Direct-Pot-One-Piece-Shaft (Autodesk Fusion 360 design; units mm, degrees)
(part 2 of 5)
sketch "M5 stop reinforcement bolt" plane through (-36.1, 0, 0) normal (1, 0, 0) x axis (0, 0, -1)
  circle C1 centre (-79.6754, -33.9652) radius 2.7
extrude "Extrude12" cut sketch "M5 stop reinforcement bolt" along normal blind 27.2
work_plane "WorkPlane13" AlongDistance -15.4 ExtraOffset 0
sketch "M5 captive stop nut" plane through (-15.4, 0, 0) normal (1, 0, 0) x axis (0, 0, -1)
  line L1 (-83.8754, -31.5403) -> (-79.6754, -29.1154)
  line L2 (-83.8754, -36.39) -> (-83.8754, -31.5403)
  line L3 (-79.6754, -38.8149) -> (-83.8754, -36.39)
  line L4 (-75.4754, -36.39) -> (-79.6754, -38.8149)
  line L5 (-75.4754, -31.5403) -> (-75.4754, -36.39)
  line L6 (-79.6754, -29.1154) -> (-75.4754, -31.5403)
extrude "Extrude13" cut sketch "M5 captive stop nut" along normal blind 6.5
work_plane "WorkPlane14" AlongDistance -36 ExtraOffset 0
sketch "Broad stop support ear (1)" plane through (-36, 0, 0) normal (1, 0, 0) x axis (0, 0, -1)
  line L1 (-60, 44) -> (-60, 20)
  line L2 (-90, 44) -> (-60, 44)
  line L3 (-90, 20) -> (-90, 44)
  line L4 (-60, 20) -> (-90, 20)
extrude "Extrude14" add sketch "Broad stop support ear (1)" along normal blind 12
work_plane "WorkPlane15" AlongDistance -24 ExtraOffset 0
sketch "Integrated steel-core end stop (1)" plane through (-24, 0, 0) normal (1, 0, 0) x axis (0, 0, -1)
  circle C1 centre (-79.6754, 33.9652) radius 6
extrude "Extrude15" add sketch "Integrated steel-core end stop (1)" along normal blind 15
work_plane "WorkPlane16" AlongDistance -36.1 ExtraOffset 0
sketch "M5 stop reinforcement bolt (1)" plane through (-36.1, 0, 0) normal (1, 0, 0) x axis (0, 0, -1)
  circle C1 centre (-79.6754, 33.9652) radius 2.7
extrude "Extrude16" cut sketch "M5 stop reinforcement bolt (1)" along normal blind 27.2
work_plane "WorkPlane17" AlongDistance -15.4 ExtraOffset 0
sketch "M5 captive stop nut (1)" plane through (-15.4, 0, 0) normal (1, 0, 0) x axis (0, 0, -1)
  line L1 (-83.8754, 36.39) -> (-79.6754, 38.8149)
  line L2 (-83.8754, 31.5403) -> (-83.8754, 36.39)
  line L3 (-79.6754, 29.1154) -> (-83.8754, 31.5403)
  line L4 (-75.4754, 31.5403) -> (-79.6754, 29.1154)
  line L5 (-75.4754, 36.39) -> (-75.4754, 31.5403)
  line L6 (-79.6754, 38.8149) -> (-75.4754, 36.39)
extrude "Extrude17" cut sketch "M5 captive stop nut (1)" along normal blind 6.5
work_plane "WorkPlane13" AlongDistance -24 ExtraOffset 0
sketch "Restore shaft socket through stop-lug root" plane through (-24, 0, 0) normal (1, 0, 0) x axis (0, 0, -1)
  line L1 (-69.6247, 6.65) -> (-60.3753, 6.65)
  arc A1 centre (-65, 0) radius 8.1 clockwise from (-60.3753, 6.65) to (-69.6247, 6.65)
extrude "Extrude13" cut sketch "Restore shaft socket through stop-lug root" along normal blind 48
work_plane "WorkPlane10" AlongDistance -24.1 ExtraOffset 0
sketch "Cam sweep clearance through crossblock" plane through (-24.1, 0, 0) normal (1, 0, 0) x axis (0, 0, -1)
  circle C1 centre (-65, 0) radius 51
extrude "Extrude10" cut sketch "Cam sweep clearance through crossblock" along normal blind 48.2
work_plane "WorkPlane10" AlongDistance 36 ExtraOffset 0
sketch "Rigid sensor carriage support" plane through (36, 0, 0) normal (1, 0, 0) x axis (0, 0, -1)
  line L1 (-49, -18) -> (-49, -28)
  line L2 (-81, -18) -> (-49, -18)
  line L3 (-81, -28) -> (-81, -18)
  line L4 (-49, -28) -> (-81, -28)
extrude "Extrude10" add sketch "Rigid sensor carriage support" along normal blind 44
work_plane "WorkPlane11" AlongDistance -28.1 ExtraOffset 0
sketch "M3 sensor carriage heat set" plane through (0, -28.1, 0) normal (0, 1, 0) x axis (1, 0, 0)
  circle C1 centre (74, -65) radius 2
extrude "Extrude11" cut sketch "M3 sensor carriage heat set" along normal blind 6.8
work_plane "WorkPlane12" AlongDistance 36 ExtraOffset 0
sketch "Rigid sensor carriage support (1)" plane through (36, 0, 0) normal (1, 0, 0) x axis (0, 0, -1)
  line L1 (-49, 28) -> (-49, 18)
  line L2 (-81, 28) -> (-49, 28)
  line L3 (-81, 18) -> (-81, 28)
  line L4 (-49, 18) -> (-81, 18)
extrude "Extrude12" add sketch "Rigid sensor carriage support (1)" along normal blind 44
work_plane "WorkPlane13" AlongDistance 21.3 ExtraOffset 0
sketch "M3 sensor carriage heat set (1)" plane through (0, 21.3, 0) normal (0, 1, 0) x axis (1, 0, 0)
  circle C1 centre (74, -65) radius 2
extrude "Extrude13" cut sketch "M3 sensor carriage heat set (1)" along normal blind 6.8
work_plane "WorkPlane1" AlongDistance -24 ExtraOffset 0
sketch "Controlled follower end float" plane through (-24, 0, 0) normal (1, 0, 0) x axis (0, 0, -1)
  circle C1 centre (-12, -35) radius 6
extrude "Extrude1" new body sketch "Controlled follower end float" along normal blind 27.8 bodies "P21 Follower left axial spacer"
work_plane "WorkPlane2" AlongDistance -24.1 ExtraOffset 0
sketch "Pivot sleeve running clearance" plane through (-24.1, 0, 0) normal (1, 0, 0) x axis (0, 0, -1)
  circle C1 centre (-12, -35) radius 4.2
extrude "Extrude2" cut sketch "Pivot sleeve running clearance" along normal blind 28
work_plane "WorkPlane1" AlongDistance 20.2 ExtraOffset 0
sketch "Controlled follower end float" plane through (20.2, 0, 0) normal (1, 0, 0) x axis (0, 0, -1)
  circle C1 centre (-12, -35) radius 6
extrude "Extrude1" new body sketch "Controlled follower end float" along normal blind 3.8 bodies "P22 Follower right axial spacer"
work_plane "WorkPlane2" AlongDistance 20.1 ExtraOffset 0
sketch "Pivot sleeve running clearance" plane through (20.1, 0, 0) normal (1, 0, 0) x axis (0, 0, -1)
  circle C1 centre (-12, -35) radius 4.2
extrude "Extrude2" cut sketch "Pivot sleeve running clearance" along normal blind 4
work_plane "WorkPlane1" AlongDistance 3.1 ExtraOffset 0
sketch "Roller axle M3 nut" plane through (3.1, 0, 0) normal (1, 0, 0) x axis (0, 0, -1)
  line L1 (-14.75, 1.5877) -> (-12, 3.1754)
  line L2 (-14.75, -1.5877) -> (-14.75, 1.5877)
  line L3 (-12, -3.1754) -> (-14.75, -1.5877)
  line L4 (-9.25, -1.5877) -> (-12, -3.1754)
  line L5 (-9.25, 1.5877) -> (-9.25, -1.5877)
  line L6 (-12, 3.1754) -> (-9.25, 1.5877)
extrude "Extrude1" new body sketch "Roller axle M3 nut" along normal blind 2.4 bodies "HARDWARE Roller axle M3 nut"
work_plane "WorkPlane2" AlongDistance 3 ExtraOffset 0
sketch "Thread envelope" plane through (3, 0, 0) normal (1, 0, 0) x axis (0, 0, -1)
  circle C1 centre (-12, 0) radius 1.5
extrude "Extrude2" cut sketch "Thread envelope" along normal blind 2.6
work_plane "WorkPlane14" AlongDistance 23.9 ExtraOffset 0
sketch "Cam lateral service opening" plane through (23.9, 0, 0) normal (1, 0, 0) x axis (0, 0, -1)
  line L1 (-42.2047, 46.7373) -> (-43.8497, 47.5044)
  line L2 (-40.5875, 45.9133) -> (-42.2047, 46.7373)
  line L3 (-39, 45.0333) -> (-40.5875, 45.9133)
  line L4 (-37.4442, 44.0985) -> (-39, 45.0333)
  line L5 (-35.922, 43.11) -> (-37.4442, 44.0985)
  line L6 (-34.4352, 42.0689) -> (-35.922, 43.11)
  line L7 (-32.9856, 40.9766) -> (-34.4352, 42.0689)
  line L8 (-31.575, 39.8343) -> (-32.9856, 40.9766)
  line L9 (-30.2052, 38.6435) -> (-31.575, 39.8343)
  line L10 (-28.8778, 37.4057) -> (-30.2052, 38.6435)
  line L11 (-27.5943, 36.1222) -> (-28.8778, 37.4057)
  line L12 (-26.3565, 34.7948) -> (-27.5943, 36.1222)
  line L13 (-25.1657, 33.425) -> (-26.3565, 34.7948)
  line L14 (-24.0234, 32.0144) -> (-25.1657, 33.425)
  line L15 (-22.9311, 30.5648) -> (-24.0234, 32.0144)
  line L16 (-21.89, 29.078) -> (-22.9311, 30.5648)
  line L17 (-20.9015, 27.5558) -> (-21.89, 29.078)
  line L18 (-19.9667, 26) -> (-20.9015, 27.5558)
  line L19 (-19.0867, 24.4125) -> (-19.9667, 26)
  line L20 (-18.2627, 22.7953) -> (-19.0867, 24.4125)
  line L21 (-17.4956, 21.1503) -> (-18.2627, 22.7953)
  line L22 (-16.7864, 19.4795) -> (-17.4956, 21.1503)
  line L23 (-16.136, 17.785) -> (-16.7864, 19.4795)
  line L24 (-15.5451, 16.0689) -> (-16.136, 17.785)
  line L25 (-15.0144, 14.3331) -> (-15.5451, 16.0689)
  line L26 (-14.5446, 12.5799) -> (-15.0144, 14.3331)
  line L27 (-14.1363, 10.8114) -> (-14.5446, 12.5799)
  line L28 (-13.79, 9.0297) -> (-14.1363, 10.8114)
  line L29 (-13.5061, 7.237) -> (-13.79, 9.0297)
  line L30 (-13.2849, 5.4355) -> (-13.5061, 7.237)
  line L31 (-13.1267, 3.6273) -> (-13.2849, 5.4355)
  line L32 (-13.0317, 1.8148) -> (-13.1267, 3.6273)
  line L33 (-13, 0) -> (-13.0317, 1.8148)
  line L34 (-13.0317, -1.8148) -> (-13, 0)
  line L35 (-13.1267, -3.6273) -> (-13.0317, -1.8148)
  line L36 (-13.2849, -5.4355) -> (-13.1267, -3.6273)
  line L37 (-13.5061, -7.237) -> (-13.2849, -5.4355)
  line L38 (-13.79, -9.0297) -> (-13.5061, -7.237)
  line L39 (-14.1363, -10.8114) -> (-13.79, -9.0297)
  line L40 (-14.5446, -12.5799) -> (-14.1363, -10.8114)
  line L41 (-15.0144, -14.3331) -> (-14.5446, -12.5799)
  line L42 (-15.5451, -16.0689) -> (-15.0144, -14.3331)
  line L43 (-16.136, -17.785) -> (-15.5451, -16.0689)
  line L44 (-16.7864, -19.4795) -> (-16.136, -17.785)
  line L45 (-17.4956, -21.1503) -> (-16.7864, -19.4795)
  line L46 (-18.2627, -22.7953) -> (-17.4956, -21.1503)
  line L47 (-19.0867, -24.4125) -> (-18.2627, -22.7953)
  line L48 (-19.9667, -26) -> (-19.0867, -24.4125)
  line L49 (-20.9015, -27.5558) -> (-19.9667, -26)
  line L50 (-21.89, -29.078) -> (-20.9015, -27.5558)
  line L51 (-22.9311, -30.5648) -> (-21.89, -29.078)
  line L52 (-24.0234, -32.0144) -> (-22.9311, -30.5648)
  line L53 (-25.1657, -33.425) -> (-24.0234, -32.0144)
  line L54 (-26.3565, -34.7948) -> (-25.1657, -33.425)
  line L55 (-27.5943, -36.1222) -> (-26.3565, -34.7948)
  line L56 (-28.8778, -37.4057) -> (-27.5943, -36.1222)
  line L57 (-30.2052, -38.6435) -> (-28.8778, -37.4057)
  line L58 (-31.575, -39.8343) -> (-30.2052, -38.6435)
  line L59 (-32.9856, -40.9766) -> (-31.575, -39.8343)
  line L60 (-34.4352, -42.0689) -> (-32.9856, -40.9766)
  line L61 (-35.922, -43.11) -> (-34.4352, -42.0689)
  line L62 (-37.4442, -44.0985) -> (-35.922, -43.11)
  line L63 (-39, -45.0333) -> (-37.4442, -44.0985)
  line L64 (-40.5875, -45.9133) -> (-39, -45.0333)
  line L65 (-42.2047, -46.7373) -> (-40.5875, -45.9133)
  line L66 (-43.8497, -47.5044) -> (-42.2047, -46.7373)
  line L67 (-54.4248, -23.7522) -> (-43.8497, -47.5044)
  line L68 (-53.6024, -23.3686) -> (-54.4248, -23.7522)
  line L69 (-52.7937, -22.9566) -> (-53.6024, -23.3686)
  line L70 (-52, -22.5167) -> (-52.7937, -22.9566)
  line L71 (-51.2221, -22.0493) -> (-52, -22.5167)
  line L72 (-50.461, -21.555) -> (-51.2221, -22.0493)
  line L73 (-49.7176, -21.0344) -> (-50.461, -21.555)
  line L74 (-48.9928, -20.4883) -> (-49.7176, -21.0344)
  line L75 (-48.2875, -19.9172) -> (-48.9928, -20.4883)
  line L76 (-47.6026, -19.3218) -> (-48.2875, -19.9172)
  line L77 (-46.9389, -18.7028) -> (-47.6026, -19.3218)
  line L78 (-46.2972, -18.0611) -> (-46.9389, -18.7028)
  line L79 (-45.6782, -17.3974) -> (-46.2972, -18.0611)
  line L80 (-45.0828, -16.7125) -> (-45.6782, -17.3974)
  line L81 (-44.5117, -16.0072) -> (-45.0828, -16.7125)
  line L82 (-43.9656, -15.2824) -> (-44.5117, -16.0072)
  line L83 (-43.445, -14.539) -> (-43.9656, -15.2824)
  line L84 (-42.9507, -13.7779) -> (-43.445, -14.539)
  line L85 (-42.4833, -13) -> (-42.9507, -13.7779)
  line L86 (-42.0434, -12.2063) -> (-42.4833, -13)
  line L87 (-41.6314, -11.3976) -> (-42.0434, -12.2063)
  line L88 (-41.2478, -10.5752) -> (-41.6314, -11.3976)
  line L89 (-40.8932, -9.7398) -> (-41.2478, -10.5752)
  line L90 (-40.568, -8.8925) -> (-40.8932, -9.7398)
  line L91 (-40.2725, -8.0344) -> (-40.568, -8.8925)
  line L92 (-40.0072, -7.1666) -> (-40.2725, -8.0344)
  line L93 (-39.7723, -6.29) -> (-40.0072, -7.1666)
  line L94 (-39.5682, -5.4057) -> (-39.7723, -6.29)
  line L95 (-39.395, -4.5149) -> (-39.5682, -5.4057)
  line L96 (-39.253, -3.6185) -> (-39.395, -4.5149)
  line L97 (-39.1424, -2.7177) -> (-39.253, -3.6185)
  line L98 (-39.0633, -1.8137) -> (-39.1424, -2.7177)
  line L99 (-39.0158, -0.9074) -> (-39.0633, -1.8137)
  line L100 (-39, 0) -> (-39.0158, -0.9074)
  line L101 (-39.0158, 0.9074) -> (-39, 0)
  line L102 (-39.0633, 1.8137) -> (-39.0158, 0.9074)
  line L103 (-39.1424, 2.7177) -> (-39.0633, 1.8137)
  line L104 (-39.253, 3.6185) -> (-39.1424, 2.7177)
  line L105 (-39.395, 4.5149) -> (-39.253, 3.6185)
  line L106 (-39.5682, 5.4057) -> (-39.395, 4.5149)
  line L107 (-39.7723, 6.29) -> (-39.5682, 5.4057)
  line L108 (-40.0072, 7.1666) -> (-39.7723, 6.29)
  line L109 (-40.2725, 8.0344) -> (-40.0072, 7.1666)
  line L110 (-40.568, 8.8925) -> (-40.2725, 8.0344)
  line L111 (-40.8932, 9.7398) -> (-40.568, 8.8925)
  line L112 (-41.2478, 10.5752) -> (-40.8932, 9.7398)
  line L113 (-41.6314, 11.3976) -> (-41.2478, 10.5752)
  line L114 (-42.0434, 12.2063) -> (-41.6314, 11.3976)
  line L115 (-42.4833, 13) -> (-42.0434, 12.2063)
  line L116 (-42.9507, 13.7779) -> (-42.4833, 13)
  line L117 (-43.445, 14.539) -> (-42.9507, 13.7779)
  line L118 (-43.9656, 15.2824) -> (-43.445, 14.539)
  line L119 (-44.5117, 16.0072) -> (-43.9656, 15.2824)
  line L120 (-45.0828, 16.7125) -> (-44.5117, 16.0072)
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extrude "Extrude14" cut sketch "Cam lateral service opening" along normal blind 12.2
work_plane "WorkPlane15" AlongDistance 36 ExtraOffset 0
sketch "Clear service path beneath sensor rails" plane through (36, 0, 0) normal (1, 0, 0) x axis (0, 0, -1)
  line L1 (-48.9, -18) -> (-48.9, -28)
  line L2 (-56, -18) -> (-48.9, -18)
  line L3 (-56, -28) -> (-56, -18)
  line L4 (-48.9, -28) -> (-56, -28)
extrude "Extrude15" cut sketch "Clear service path beneath sensor rails" along normal blind 44.1
work_plane "WorkPlane16" AlongDistance 36 ExtraOffset 0
sketch "Clear service path beneath sensor rails (1)" plane through (36, 0, 0) normal (1, 0, 0) x axis (0, 0, -1)
  line L1 (-48.9, 28) -> (-48.9, 18)
  line L2 (-56, 28) -> (-48.9, 28)
  line L3 (-56, 18) -> (-56, 28)
  line L4 (-48.9, 18) -> (-56, 18)
extrude "Extrude16" cut sketch "Clear service path beneath sensor rails (1)" along normal blind 44.1
work_plane "WorkPlane11" AlongDistance -24 ExtraOffset 0
sketch "Raise mount clear of rail bolt axes" plane through (-24, 0, 0) normal (1, 0, 0) x axis (0, 0, -1)
  line L1 (-52, -44) -> (-52, -66)
  line L2 (-57, -44) -> (-52, -44)
  line L3 (-57, -66) -> (-57, -44)
  line L4 (-52, -66) -> (-57, -66)
extrude "Extrude11" add sketch "Raise mount clear of rail bolt axes" along normal blind 48
work_plane "WorkPlane12" AlongDistance -24 ExtraOffset 0
sketch "Close old block mounting hole" plane through (-24, 0, 0) normal (1, 0, 0) x axis (0, 0, -1)
  circle C1 centre (-44, -59) radius 2.01
extrude "Extrude12" add sketch "Close old block mounting hole" along normal blind 8.7
work_plane "WorkPlane13" AlongDistance -24.1 ExtraOffset 0
sketch "Raised M3 block insert" plane through (-24.1, 0, 0) normal (1, 0, 0) x axis (0, 0, -1)
  circle C1 centre (-52, -59) radius 2
extrude "Extrude13" cut sketch "Raised M3 block insert" along normal blind 8.9
work_plane "WorkPlane14" AlongDistance 15.3 ExtraOffset 0
sketch "Close old block mounting hole (1)" plane through (15.3, 0, 0) normal (1, 0, 0) x axis (0, 0, -1)
  circle C1 centre (-44, -59) radius 2.01
extrude "Extrude14" add sketch "Close old block mounting hole (1)" along normal blind 8.7
work_plane "WorkPlane15" AlongDistance 15.2 ExtraOffset 0
sketch "Raised M3 block insert (1)" plane through (15.2, 0, 0) normal (1, 0, 0) x axis (0, 0, -1)
  circle C1 centre (-52, -59) radius 2
extrude "Extrude15" cut sketch "Raised M3 block insert (1)" along normal blind 8.9
work_plane "WorkPlane18" AlongDistance -36 ExtraOffset 0
sketch "Close old plate mounting hole" plane through (-36, 0, 0) normal (1, 0, 0) x axis (0, 0, -1)
  circle C1 centre (-44, -59) radius 1.71
extrude "Extrude18" add sketch "Close old plate mounting hole" along normal blind 12
work_plane "WorkPlane19" AlongDistance -36.1 ExtraOffset 0
sketch "Raised M3 block fastener" plane through (-36.1, 0, 0) normal (1, 0, 0) x axis (0, 0, -1)
  circle C1 centre (-52, -59) radius 1.7
extrude "Extrude19" cut sketch "Raised M3 block fastener" along normal blind 12.2
work_plane "WorkPlane17" AlongDistance 24 ExtraOffset 0
sketch "Close old plate mounting hole" plane through (24, 0, 0) normal (1, 0, 0) x axis (0, 0, -1)
  circle C1 centre (-44, -59) radius 1.71
extrude "Extrude17" add sketch "Close old plate mounting hole" along normal blind 12
work_plane "WorkPlane18" AlongDistance 23.9 ExtraOffset 0
sketch "Raised M3 block fastener" plane through (23.9, 0, 0) normal (1, 0, 0) x axis (0, 0, -1)
  circle C1 centre (-52, -59) radius 1.7
extrude "Extrude18" cut sketch "Raised M3 block fastener" along normal blind 12.2
work_plane "WorkPlane16" AlongDistance -24 ExtraOffset 0
sketch "Close old block mounting hole (2)" plane through (-24, 0, 0) normal (1, 0, 0) x axis (0, 0, -1)
  circle C1 centre (-44, -51) radius 2.01
extrude "Extrude16" add sketch "Close old block mounting hole (2)" along normal blind 8.7
work_plane "WorkPlane17" AlongDistance -24.1 ExtraOffset 0
sketch "Raised M3 block insert (2)" plane through (-24.1, 0, 0) normal (1, 0, 0) x axis (0, 0, -1)
  circle C1 centre (-52, -51) radius 2
extrude "Extrude17" cut sketch "Raised M3 block insert (2)" along normal blind 8.9
work_plane "WorkPlane18" AlongDistance 15.3 ExtraOffset 0
sketch "Close old block mounting hole (3)" plane through (15.3, 0, 0) normal (1, 0, 0) x axis (0, 0, -1)
  circle C1 centre (-44, -51) radius 2.01
extrude "Extrude18" add sketch "Close old block mounting hole (3)" along normal blind 8.7
work_plane "WorkPlane19" AlongDistance 15.2 ExtraOffset 0
sketch "Raised M3 block insert (3)" plane through (15.2, 0, 0) normal (1, 0, 0) x axis (0, 0, -1)
  circle C1 centre (-52, -51) radius 2
extrude "Extrude19" cut sketch "Raised M3 block insert (3)" along normal blind 8.9
work_plane "WorkPlane20" AlongDistance -36 ExtraOffset 0
sketch "Close old plate mounting hole (1)" plane through (-36, 0, 0) normal (1, 0, 0) x axis (0, 0, -1)
  circle C1 centre (-44, -51) radius 1.71
extrude "Extrude20" add sketch "Close old plate mounting hole (1)" along normal blind 12
work_plane "WorkPlane21" AlongDistance -36.1 ExtraOffset 0
sketch "Raised M3 block fastener (1)" plane through (-36.1, 0, 0) normal (1, 0, 0) x axis (0, 0, -1)
  circle C1 centre (-52, -51) radius 1.7
extrude "Extrude21" cut sketch "Raised M3 block fastener (1)" along normal blind 12.2
work_plane "WorkPlane19" AlongDistance 24 ExtraOffset 0
sketch "Close old plate mounting hole (1)" plane through (24, 0, 0) normal (1, 0, 0) x axis (0, 0, -1)
  circle C1 centre (-44, -51) radius 1.71
extrude "Extrude19" add sketch "Close old plate mounting hole (1)" along normal blind 12
work_plane "WorkPlane20" AlongDistance 23.9 ExtraOffset 0
sketch "Raised M3 block fastener (1)" plane through (23.9, 0, 0) normal (1, 0, 0) x axis (0, 0, -1)
  circle C1 centre (-52, -51) radius 1.7
extrude "Extrude20" cut sketch "Raised M3 block fastener (1)" along normal blind 12.2
work_plane "WorkPlane20" AlongDistance 51.9 ExtraOffset 0
sketch "Continue adjuster bore" plane through (0, 0, 51.9) normal (0, 0, 1) x axis (1, 0, 0)
  circle C1 centre (12, -55) radius 2.2
extrude "Extrude20" cut sketch "Continue adjuster bore" along normal blind 5.2
work_plane "WorkPlane21" AlongDistance 51.9 ExtraOffset 0
sketch "Continue guide bore" plane through (0, 0, 51.9) normal (0, 0, 1) x axis (1, 0, 0)
  circle C1 centre (5, -55) radius 1.7
extrude "Extrude21" cut sketch "Continue guide bore" along normal blind 5.2
work_plane "WorkPlane22" AlongDistance 51.9 ExtraOffset 0
sketch "Continue guide bore (1)" plane through (0, 0, 51.9) normal (0, 0, 1) x axis (1, 0, 0)
  circle C1 centre (19, -55) radius 1.7
extrude "Extrude22" cut sketch "Continue guide bore (1)" along normal blind 5.2
work_plane "WorkPlane23" AlongDistance -24.1 ExtraOffset 0
sketch "Preserve cam sweep clearance" plane through (-24.1, 0, 0) normal (1, 0, 0) x axis (0, 0, -1)
  circle C1 centre (-65, 0) radius 51
extrude "Extrude23" cut sketch "Preserve cam sweep clearance" along normal blind 48.2
work_plane "WorkPlane1" AlongDistance -23.85 ExtraOffset 0
sketch "Controlled rotor axial clearance" plane through (-23.85, 0, 0) normal (1, 0, 0) x axis (0, 0, -1)
  circle C1 centre (-65, 0) radius 10
extrude "Extrude1" new body sketch "Controlled rotor axial clearance" along normal blind 16.85 bodies "P23 Left rotor thrust spacer"
work_plane "WorkPlane2" AlongDistance -23.95 ExtraOffset 0
sketch "Free spacer bore" plane through (-23.95, 0, 0) normal (1, 0, 0) x axis (0, 0, -1)
  circle C1 centre (-65, 0) radius 8.2
extrude "Extrude2" cut sketch "Free spacer bore" along normal blind 17.05
work_plane "WorkPlane1" AlongDistance 7 ExtraOffset 0
sketch "Controlled rotor axial clearance" plane through (7, 0, 0) normal (1, 0, 0) x axis (0, 0, -1)
  circle C1 centre (-65, 0) radius 10
extrude "Extrude1" new body sketch "Controlled rotor axial clearance" along normal blind 16.85 bodies "P24 Right rotor thrust spacer"
work_plane "WorkPlane2" AlongDistance 6.9 ExtraOffset 0
sketch "Free spacer bore" plane through (6.9, 0, 0) normal (1, 0, 0) x axis (0, 0, -1)
  circle C1 centre (-65, 0) radius 8.2
extrude "Extrude2" cut sketch "Free spacer bore" along normal blind 17.05
work_plane "WorkPlane22" AlongDistance -76 ExtraOffset 0
sketch "Restore rail bolt clearance after hole filling" plane through (0, -76, 0) normal (0, 1, 0) x axis (1, 0, 0)
  circle C1 centre (-30, -45) radius 2.7
extrude "Extrude22" cut sketch "Restore rail bolt clearance after hole filling" along normal blind 22
work_plane "WorkPlane23" AlongDistance 54 ExtraOffset 0
sketch "Restore rail bolt clearance after hole filling (1)" plane through (0, 54, 0) normal (0, 1, 0) x axis (1, 0, 0)
  circle C1 centre (-30, -45) radius 2.7
work_plane "WorkPlane24" AlongDistance -55 ExtraOffset 0
sketch "Restore rail head access after hole filling" plane through (0, -55, 0) normal (0, 1, 0) x axis (1, 0, 0)
  circle C1 centre (-30, -45) radius 5.3
extrude "Extrude24" cut sketch "Restore rail head access after hole filling" along normal blind 12
work_plane "WorkPlane25" AlongDistance 43 ExtraOffset 0
sketch "Restore rail head access after hole filling (1)" plane through (0, 43, 0) normal (0, 1, 0) x axis (1, 0, 0)
  circle C1 centre (-30, -45) radius 5.3
work_plane "WorkPlane21" AlongDistance -76 ExtraOffset 0
sketch "Restore rail bolt clearance after hole filling" plane through (0, -76, 0) normal (0, 1, 0) x axis (1, 0, 0)
  circle C1 centre (30, -45) radius 2.7
extrude "Extrude21" cut sketch "Restore rail bolt clearance after hole filling" along normal blind 22
work_plane "WorkPlane22" AlongDistance 54 ExtraOffset 0
sketch "Restore rail bolt clearance after hole filling (1)" plane through (0, 54, 0) normal (0, 1, 0) x axis (1, 0, 0)
  circle C1 centre (30, -45) radius 2.7
work_plane "WorkPlane23" AlongDistance -55 ExtraOffset 0
sketch "Restore rail head access after hole filling" plane through (0, -55, 0) normal (0, 1, 0) x axis (1, 0, 0)
  circle C1 centre (30, -45) radius 5.3
extrude "Extrude23" cut sketch "Restore rail head access after hole filling" along normal blind 12
work_plane "WorkPlane24" AlongDistance 43 ExtraOffset 0
sketch "Restore rail head access after hole filling (1)" plane through (0, 43, 0) normal (0, 1, 0) x axis (1, 0, 0)
  circle C1 centre (30, -45) radius 5.3
work_plane "WorkPlane14" AlongDistance -18.1 ExtraOffset 0
sketch "Stop lug clearance for concentric thrust spacer" plane through (-18.1, 0, 0) normal (1, 0, 0) x axis (0, 0, -1)
  circle C1 centre (-65, 0) radius 10.2
extrude "Extrude14" cut sketch "Stop lug clearance for concentric thrust spacer" along normal blind 11
work_plane "WorkPlane15" AlongDistance -18.1 ExtraOffset 0
sketch "Complete stop lug relief to rotor face" plane through (-18.1, 0, 0) normal (1, 0, 0) x axis (0, 0, -1)
  circle C1 centre (-65, 0) radius 10.2
extrude "Extrude15" cut sketch "Complete stop lug relief to rotor face" along normal blind 11.1
ground "Pin2"
ground "Pin3"
ground "Pin4"
ground "Pin5"
ground "Pin6"
ground "Pin11"
ground "Pin12"
ground "Pin48"
ground "Pin49"
work_plane "WorkPlane24" AlongDistance -24 ExtraOffset 0
sketch "Extra roof over relocated heat-set inserts" plane through (-24, 0, 0) normal (1, 0, 0) x axis (0, 0, -1)
  line L1 (-57, -44) -> (-57, -66)
  line L2 (-59, -44) -> (-57, -44)
  line L3 (-59, -66) -> (-59, -44)
  line L4 (-57, -66) -> (-59, -66)
extrude "Extrude24" add sketch "Extra roof over relocated heat-set inserts" along normal blind 48
work_plane "WorkPlane25" AlongDistance -24 ExtraOffset 0
sketch "Fill former insert location" plane through (-24, 0, 0) normal (1, 0, 0) x axis (0, 0, -1)
  circle C1 centre (-52, -59) radius 2.01
extrude "Extrude25" add sketch "Fill former insert location" along normal blind 8.7
work_plane "WorkPlane26" AlongDistance 15.3 ExtraOffset 0
sketch "Fill former insert location (1)" plane through (15.3, 0, 0) normal (1, 0, 0) x axis (0, 0, -1)
  circle C1 centre (-52, -59) radius 2.01
extrude "Extrude26" add sketch "Fill former insert location (1)" along normal blind 8.7
work_plane "WorkPlane26" AlongDistance -36 ExtraOffset 0
sketch "Fill former plate mounting hole" plane through (-36, 0, 0) normal (1, 0, 0) x axis (0, 0, -1)
  circle C1 centre (-52, -59) radius 1.71
extrude "Extrude26" add sketch "Fill former plate mounting hole" along normal blind 12
work_plane "WorkPlane25" AlongDistance 24 ExtraOffset 0
sketch "Fill former plate mounting hole" plane through (24, 0, 0) normal (1, 0, 0) x axis (0, 0, -1)
  circle C1 centre (-52, -59) radius 1.71
extrude "Extrude25" add sketch "Fill former plate mounting hole" along normal blind 12
work_plane "WorkPlane27" AlongDistance -24 ExtraOffset 0
sketch "Fill former insert location (2)" plane through (-24, 0, 0) normal (1, 0, 0) x axis (0, 0, -1)
  circle C1 centre (-52, -51) radius 2.01
extrude "Extrude27" add sketch "Fill former insert location (2)" along normal blind 8.7
work_plane "WorkPlane28" AlongDistance 15.3 ExtraOffset 0
sketch "Fill former insert location (3)" plane through (15.3, 0, 0) normal (1, 0, 0) x axis (0, 0, -1)
  circle C1 centre (-52, -51) radius 2.01
extrude "Extrude28" add sketch "Fill former insert location (3)" along normal blind 8.7
work_plane "WorkPlane27" AlongDistance -36 ExtraOffset 0
sketch "Fill former plate mounting hole (1)" plane through (-36, 0, 0) normal (1, 0, 0) x axis (0, 0, -1)
  circle C1 centre (-52, -51) radius 1.71
extrude "Extrude27" add sketch "Fill former plate mounting hole (1)" along normal blind 12
work_plane "WorkPlane26" AlongDistance 24 ExtraOffset 0
sketch "Fill former plate mounting hole (1)" plane through (24, 0, 0) normal (1, 0, 0) x axis (0, 0, -1)
  circle C1 centre (-52, -51) radius 1.71
extrude "Extrude26" add sketch "Fill former plate mounting hole (1)" along normal blind 12
work_plane "WorkPlane29" AlongDistance -24.1 ExtraOffset 0
sketch "Relocated insert with cam-side retaining wall" plane through (-24.1, 0, 0) normal (1, 0, 0) x axis (0, 0, -1)
  circle C1 centre (-53.5, -62) radius 2
extrude "Extrude29" cut sketch "Relocated insert with cam-side retaining wall" along normal blind 8.9
work_plane "WorkPlane30" AlongDistance 15.3 ExtraOffset 0
sketch "Relocated insert with cam-side retaining wall (1)" plane through (15.3, 0, 0) normal (1, 0, 0) x axis (0, 0, -1)
  circle C1 centre (-53.5, -62) radius 2
extrude "Extrude30" cut sketch "Relocated insert with cam-side retaining wall (1)" along normal blind 8.9
work_plane "WorkPlane28" AlongDistance -36.1 ExtraOffset 0
sketch "Relocated mount above rail counterbore" plane through (-36.1, 0, 0) normal (1, 0, 0) x axis (0, 0, -1)
  circle C1 centre (-53.5, -62) radius 1.7
extrude "Extrude28" cut sketch "Relocated mount above rail counterbore" along normal blind 12.2
work_plane "WorkPlane27" AlongDistance 23.9 ExtraOffset 0
sketch "Relocated mount above rail counterbore" plane through (23.9, 0, 0) normal (1, 0, 0) x axis (0, 0, -1)
  circle C1 centre (-53.5, -62) radius 1.7
extrude "Extrude27" cut sketch "Relocated mount above rail counterbore" along normal blind 12.2
work_plane "WorkPlane31" AlongDistance -24.1 ExtraOffset 0
sketch "Relocated insert with cam-side retaining wall (2)" plane through (-24.1, 0, 0) normal (1, 0, 0) x axis (0, 0, -1)
  circle C1 centre (-53.5, -54) radius 2
extrude "Extrude31" cut sketch "Relocated insert with cam-side retaining wall (2)" along normal blind 8.9
work_plane "WorkPlane32" AlongDistance 15.3 ExtraOffset 0
sketch "Relocated insert with cam-side retaining wall (3)" plane through (15.3, 0, 0) normal (1, 0, 0) x axis (0, 0, -1)
  circle C1 centre (-53.5, -54) radius 2
extrude "Extrude32" cut sketch "Relocated insert with cam-side retaining wall (3)" along normal blind 8.9
work_plane "WorkPlane29" AlongDistance -36.1 ExtraOffset 0
sketch "Relocated mount above rail counterbore (1)" plane through (-36.1, 0, 0) normal (1, 0, 0) x axis (0, 0, -1)
  circle C1 centre (-53.5, -54) radius 1.7
extrude "Extrude29" cut sketch "Relocated mount above rail counterbore (1)" along normal blind 12.2
work_plane "WorkPlane28" AlongDistance 23.9 ExtraOffset 0
sketch "Relocated mount above rail counterbore (1)" plane through (23.9, 0, 0) normal (1, 0, 0) x axis (0, 0, -1)
  circle C1 centre (-53.5, -54) radius 1.7
extrude "Extrude28" cut sketch "Relocated mount above rail counterbore (1)" along normal blind 12.2
work_plane "WorkPlane33" AlongDistance 51.9 ExtraOffset 0
sketch "Continue adjuster bore through roof" plane through (0, 0, 51.9) normal (0, 0, 1) x axis (1, 0, 0)
  circle C1 centre (12, -55) radius 2.2
extrude "Extrude33" cut sketch "Continue adjuster bore through roof" along normal blind 7.2
work_plane "WorkPlane34" AlongDistance 51.9 ExtraOffset 0
sketch "Continue guide bore through roof" plane through (0, 0, 51.9) normal (0, 0, 1) x axis (1, 0, 0)
  circle C1 centre (5, -55) radius 1.7
extrude "Extrude34" cut sketch "Continue guide bore through roof" along normal blind 7.2
work_plane "WorkPlane35" AlongDistance 51.9 ExtraOffset 0
sketch "Continue guide bore through roof (1)" plane through (0, 0, 51.9) normal (0, 0, 1) x axis (1, 0, 0)
  circle C1 centre (19, -55) radius 1.7
extrude "Extrude35" cut sketch "Continue guide bore through roof (1)" along normal blind 7.2
work_plane "WorkPlane36" AlongDistance -24.1 ExtraOffset 0
sketch "Restore cam envelope after pocket repair" plane through (-24.1, 0, 0) normal (1, 0, 0) x axis (0, 0, -1)
  circle C1 centre (-65, 0) radius 51
extrude "Extrude36" cut sketch "Restore cam envelope after pocket repair" along normal blind 48.2
work_plane "WorkPlane30" AlongDistance -76 ExtraOffset 0
sketch "Preserve rail shank passage" plane through (0, -76, 0) normal (0, 1, 0) x axis (1, 0, 0)
  circle C1 centre (-30, -45) radius 2.7
work_plane "WorkPlane31" AlongDistance 54 ExtraOffset 0
sketch "Preserve rail shank passage (1)" plane through (0, 54, 0) normal (0, 1, 0) x axis (1, 0, 0)
  circle C1 centre (-30, -45) radius 2.7
work_plane "WorkPlane32" AlongDistance -55 ExtraOffset 0
sketch "Preserve rail head passage" plane through (0, -55, 0) normal (0, 1, 0) x axis (1, 0, 0)
  circle C1 centre (-30, -45) radius 5.3
extrude "Extrude32" cut sketch "Preserve rail head passage" along normal blind 12
work_plane "WorkPlane33" AlongDistance 43 ExtraOffset 0
sketch "Preserve rail head passage (1)" plane through (0, 43, 0) normal (0, 1, 0) x axis (1, 0, 0)
  circle C1 centre (-30, -45) radius 5.3
work_plane "WorkPlane29" AlongDistance -76 ExtraOffset 0
sketch "Preserve rail shank passage" plane through (0, -76, 0) normal (0, 1, 0) x axis (1, 0, 0)
  circle C1 centre (30, -45) radius 2.7
work_plane "WorkPlane30" AlongDistance 54 ExtraOffset 0
sketch "Preserve rail shank passage (1)" plane through (0, 54, 0) normal (0, 1, 0) x axis (1, 0, 0)
  circle C1 centre (30, -45) radius 2.7
work_plane "WorkPlane31" AlongDistance -55 ExtraOffset 0
sketch "Preserve rail head passage" plane through (0, -55, 0) normal (0, 1, 0) x axis (1, 0, 0)
  circle C1 centre (30, -45) radius 5.3
extrude "Extrude31" cut sketch "Preserve rail head passage" along normal blind 12
work_plane "WorkPlane32" AlongDistance 43 ExtraOffset 0
sketch "Preserve rail head passage (1)" plane through (0, 43, 0) normal (0, 1, 0) x axis (1, 0, 0)
  circle C1 centre (30, -45) radius 5.3
work_plane "WorkPlane16" AlongDistance -5 ExtraOffset 0
sketch "Flat washer seat for sensor-drive shaft clamp" plane through (-5, 0, 0) normal (1, 0, 0) x axis (0, 0, -1)
  line L1 (-60, 22) -> (-60, 20)
  line L2 (-70, 22) -> (-60, 22)
  line L3 (-70, 20) -> (-70, 22)
  line L4 (-60, 20) -> (-70, 20)
extrude "Extrude16" add sketch "Flat washer seat for sensor-drive shaft clamp" along normal blind 10
work_plane "WorkPlane17" AlongDistance 6.4 ExtraOffset 0
sketch "Radial screw onto printed shaft D flat" plane through (0, 6.4, 0) normal (0, 1, 0) x axis (1, 0, 0)
  circle C1 centre (0, -65) radius 1.7
extrude "Extrude17" cut sketch "Radial screw onto printed shaft D flat" along normal blind 15.7
work_plane "WorkPlane18" AlongDistance 15.2 ExtraOffset 0
sketch "M3 heatset pocket for rotor clamp" plane through (0, 15.2, 0) normal (0, 1, 0) x axis (1, 0, 0)
  circle C1 centre (0, -65) radius 2
work_plane "WorkPlane37" AlongDistance -24 ExtraOffset 0
sketch "Extend reaction block into free rail bay" plane through (-24, 0, 0) normal (1, 0, 0) x axis (0, 0, -1)
  line L1 (-38, -66) -> (-38, -74)
  line L2 (-59, -66) -> (-38, -66)
  line L3 (-59, -74) -> (-59, -66)
  line L4 (-38, -74) -> (-59, -74)
extrude "Extrude37" add sketch "Extend reaction block into free rail bay" along normal blind 48
work_plane "WorkPlane38" AlongDistance -24 ExtraOffset 0
sketch "Close mounting bore that crossed cup guide" plane through (-24, 0, 0) normal (1, 0, 0) x axis (0, 0, -1)
  circle C1 centre (-53.5, -54) radius 2.01
extrude "Extrude38" add sketch "Close mounting bore that crossed cup guide" along normal blind 8.7
work_plane "WorkPlane39" AlongDistance -24.1 ExtraOffset 0
sketch "Outer mounting row clear of guide" plane through (-24.1, 0, 0) normal (1, 0, 0) x axis (0, 0, -1)
  circle C1 centre (-53.5, -70) radius 2
extrude "Extrude39" cut sketch "Outer mounting row clear of guide" along normal blind 8.9
work_plane "WorkPlane40" AlongDistance 15.3 ExtraOffset 0
sketch "Close mounting bore that crossed cup guide (1)" plane through (15.3, 0, 0) normal (1, 0, 0) x axis (0, 0, -1)
  circle C1 centre (-53.5, -54) radius 2.01
extrude "Extrude40" add sketch "Close mounting bore that crossed cup guide (1)" along normal blind 8.7
work_plane "WorkPlane41" AlongDistance 15.2 ExtraOffset 0
sketch "Outer mounting row clear of guide (1)" plane through (15.2, 0, 0) normal (1, 0, 0) x axis (0, 0, -1)
  circle C1 centre (-53.5, -70) radius 2
extrude "Extrude41" cut sketch "Outer mounting row clear of guide (1)" along normal blind 8.9
work_plane "WorkPlane34" AlongDistance -36 ExtraOffset 0
sketch "Close former inner mounting hole" plane through (-36, 0, 0) normal (1, 0, 0) x axis (0, 0, -1)
  circle C1 centre (-53.5, -54) radius 1.71
extrude "Extrude34" add sketch "Close former inner mounting hole" along normal blind 12
work_plane "WorkPlane35" AlongDistance -36.1 ExtraOffset 0
sketch "Matched outer mounting row" plane through (-36.1, 0, 0) normal (1, 0, 0) x axis (0, 0, -1)
  circle C1 centre (-53.5, -70) radius 1.7
extrude "Extrude35" cut sketch "Matched outer mounting row" along normal blind 12.2
work_plane "WorkPlane33" AlongDistance 24 ExtraOffset 0
sketch "Close former inner mounting hole" plane through (24, 0, 0) normal (1, 0, 0) x axis (0, 0, -1)
  circle C1 centre (-53.5, -54) radius 1.71
extrude "Extrude33" add sketch "Close former inner mounting hole" along normal blind 12
work_plane "WorkPlane34" AlongDistance 23.9 ExtraOffset 0
sketch "Matched outer mounting row" plane through (23.9, 0, 0) normal (1, 0, 0) x axis (0, 0, -1)
  circle C1 centre (-53.5, -70) radius 1.7
extrude "Extrude34" cut sketch "Matched outer mounting row" along normal blind 12.2
work_plane "WorkPlane42" AlongDistance 37.9 ExtraOffset 0
sketch "Restore separate cup guide bore" plane through (0, 0, 37.9) normal (0, 0, 1) x axis (1, 0, 0)
  circle C1 centre (5, -55) radius 1.7
work_plane "WorkPlane43" AlongDistance 37.9 ExtraOffset 0
sketch "Restore separate cup guide bore (1)" plane through (0, 0, 37.9) normal (0, 0, 1) x axis (1, 0, 0)
  circle C1 centre (19, -55) radius 1.7
extrude "Extrude43" cut sketch "Restore separate cup guide bore (1)" along normal blind 21.2
work_plane "WorkPlane44" AlongDistance -24.1 ExtraOffset 0
sketch "Preserve cam envelope" plane through (-24.1, 0, 0) normal (1, 0, 0) x axis (0, 0, -1)
  circle C1 centre (-65, 0) radius 51
work_plane "WorkPlane36" AlongDistance -55 ExtraOffset 0
sketch "Close inaccessible rail head pocket" plane through (0, -55, 0) normal (0, 1, 0) x axis (1, 0, 0)
  circle C1 centre (-30, -45) radius 5.31
extrude "Extrude36" add sketch "Close inaccessible rail head pocket" along normal blind 12
work_plane "WorkPlane37" AlongDistance 43 ExtraOffset 0
sketch "Close inaccessible rail head pocket (1)" plane through (0, 43, 0) normal (0, 1, 0) x axis (1, 0, 0)
  circle C1 centre (-30, -45) radius 5.31
extrude "Extrude37" add sketch "Close inaccessible rail head pocket (1)" along normal blind 12
work_plane "WorkPlane38" AlongDistance -75 ExtraOffset 0
sketch "Close obsolete side rail bore" plane through (0, -75, 0) normal (0, 1, 0) x axis (1, 0, 0)
  circle C1 centre (-30, -45) radius 2.71
extrude "Extrude38" add sketch "Close obsolete side rail bore" along normal blind 20
work_plane "WorkPlane39" AlongDistance 55 ExtraOffset 0
sketch "Close obsolete side rail bore (1)" plane through (0, 55, 0) normal (0, 1, 0) x axis (1, 0, 0)
  circle C1 centre (-30, -45) radius 2.71
extrude "Extrude39" add sketch "Close obsolete side rail bore (1)" along normal blind 20
work_plane "WorkPlane40" AlongDistance -36 ExtraOffset 0
sketch "Top-access 2020 mounting flange" plane through (-36, 0, 0) normal (1, 0, 0) x axis (0, 0, -1)
  line L1 (-55, -70) -> (-55, -95)
  line L2 (-63, -70) -> (-55, -70)
  line L3 (-63, -95) -> (-63, -70)
  line L4 (-55, -95) -> (-63, -95)
extrude "Extrude40" add sketch "Top-access 2020 mounting flange" along normal blind 12
work_plane "WorkPlane41" AlongDistance -36 ExtraOffset 0
sketch "Mount root triangular reinforcement" plane through (-36, 0, 0) normal (1, 0, 0) x axis (0, 0, -1)
  line L1 (-56, -63) -> (-56, -70)
  line L2 (-63, -70) -> (-56, -63)
  line L3 (-56, -70) -> (-63, -70)
extrude "Extrude41" add sketch "Mount root triangular reinforcement" along normal blind 12
work_plane "WorkPlane42" AlongDistance 54.9 ExtraOffset 0
sketch "Vertical M5 rail mounting bore" plane through (0, 0, 54.9) normal (0, 0, 1) x axis (1, 0, 0)
  circle C1 centre (-30, -85) radius 2.7
extrude "Extrude42" cut sketch "Vertical M5 rail mounting bore" along normal blind 8.2
work_plane "WorkPlane43" AlongDistance -36 ExtraOffset 0
sketch "Top-access 2020 mounting flange (1)" plane through (-36, 0, 0) normal (1, 0, 0) x axis (0, 0, -1)
  line L1 (-55, 95) -> (-55, 70)
  line L2 (-63, 95) -> (-55, 95)
  line L3 (-63, 70) -> (-63, 95)
  line L4 (-55, 70) -> (-63, 70)
extrude "Extrude43" add sketch "Top-access 2020 mounting flange (1)" along normal blind 12
work_plane "WorkPlane44" AlongDistance -36 ExtraOffset 0
sketch "Mount root triangular reinforcement (1)" plane through (-36, 0, 0) normal (1, 0, 0) x axis (0, 0, -1)
  line L1 (-56, 70) -> (-56, 63)
  line L2 (-63, 70) -> (-56, 70)
  line L3 (-56, 63) -> (-63, 70)
extrude "Extrude44" add sketch "Mount root triangular reinforcement (1)" along normal blind 12
work_plane "WorkPlane45" AlongDistance 54.9 ExtraOffset 0
sketch "Vertical M5 rail mounting bore (1)" plane through (0, 0, 54.9) normal (0, 0, 1) x axis (1, 0, 0)
  circle C1 centre (-30, 85) radius 2.7
extrude "Extrude45" cut sketch "Vertical M5 rail mounting bore (1)" along normal blind 8.2
work_plane "WorkPlane46" AlongDistance -36 ExtraOffset 0
sketch "Close old M5 pivot clearance" plane through (-36, 0, 0) normal (1, 0, 0) x axis (0, 0, -1)
  circle C1 centre (-12, -35) radius 2.71
extrude "Extrude46" add sketch "Close old M5 pivot clearance" along normal blind 12
work_plane "WorkPlane47" AlongDistance -36.1 ExtraOffset 0
sketch "M3 follower pivot clearance" plane through (-36.1, 0, 0) normal (1, 0, 0) x axis (0, 0, -1)
  circle C1 centre (-12, -35) radius 1.7
extrude "Extrude47" cut sketch "M3 follower pivot clearance" along normal blind 12.2
work_plane "WorkPlane35" AlongDistance -55 ExtraOffset 0
sketch "Close inaccessible rail head pocket" plane through (0, -55, 0) normal (0, 1, 0) x axis (1, 0, 0)
  circle C1 centre (30, -45) radius 5.31
extrude "Extrude35" add sketch "Close inaccessible rail head pocket" along normal blind 12
work_plane "WorkPlane36" AlongDistance 43 ExtraOffset 0
sketch "Close inaccessible rail head pocket (1)" plane through (0, 43, 0) normal (0, 1, 0) x axis (1, 0, 0)
  circle C1 centre (30, -45) radius 5.31
extrude "Extrude36" add sketch "Close inaccessible rail head pocket (1)" along normal blind 12
work_plane "WorkPlane37" AlongDistance -75 ExtraOffset 0
sketch "Close obsolete side rail bore" plane through (0, -75, 0) normal (0, 1, 0) x axis (1, 0, 0)
  circle C1 centre (30, -45) radius 2.71
extrude "Extrude37" add sketch "Close obsolete side rail bore" along normal blind 20
work_plane "WorkPlane38" AlongDistance 55 ExtraOffset 0
sketch "Close obsolete side rail bore (1)" plane through (0, 55, 0) normal (0, 1, 0) x axis (1, 0, 0)
  circle C1 centre (30, -45) radius 2.71
extrude "Extrude38" add sketch "Close obsolete side rail bore (1)" along normal blind 20
work_plane "WorkPlane39" AlongDistance 24 ExtraOffset 0
sketch "Top-access 2020 mounting flange" plane through (24, 0, 0) normal (1, 0, 0) x axis (0, 0, -1)
  line L1 (-55, -70) -> (-55, -95)
  line L2 (-63, -70) -> (-55, -70)
  line L3 (-63, -95) -> (-63, -70)
  line L4 (-55, -95) -> (-63, -95)
extrude "Extrude39" add sketch "Top-access 2020 mounting flange" along normal blind 12
work_plane "WorkPlane40" AlongDistance 24 ExtraOffset 0
sketch "Mount root triangular reinforcement" plane through (24, 0, 0) normal (1, 0, 0) x axis (0, 0, -1)
  line L1 (-56, -63) -> (-56, -70)
  line L2 (-63, -70) -> (-56, -63)
  line L3 (-56, -70) -> (-63, -70)
extrude "Extrude40" add sketch "Mount root triangular reinforcement" along normal blind 12
work_plane "WorkPlane41" AlongDistance 54.9 ExtraOffset 0
sketch "Vertical M5 rail mounting bore" plane through (0, 0, 54.9) normal (0, 0, 1) x axis (1, 0, 0)
  circle C1 centre (30, -85) radius 2.7
extrude "Extrude41" cut sketch "Vertical M5 rail mounting bore" along normal blind 8.2
work_plane "WorkPlane42" AlongDistance 24 ExtraOffset 0
sketch "Top-access 2020 mounting flange (1)" plane through (24, 0, 0) normal (1, 0, 0) x axis (0, 0, -1)
  line L1 (-55, 95) -> (-55, 70)
  line L2 (-63, 95) -> (-55, 95)
  line L3 (-63, 70) -> (-63, 95)
  line L4 (-55, 70) -> (-63, 70)
extrude "Extrude42" add sketch "Top-access 2020 mounting flange (1)" along normal blind 12
work_plane "WorkPlane43" AlongDistance 24 ExtraOffset 0
sketch "Mount root triangular reinforcement (1)" plane through (24, 0, 0) normal (1, 0, 0) x axis (0, 0, -1)
  line L1 (-56, 70) -> (-56, 63)
  line L2 (-63, 70) -> (-56, 70)
  line L3 (-56, 63) -> (-63, 70)
extrude "Extrude43" add sketch "Mount root triangular reinforcement (1)" along normal blind 12
work_plane "WorkPlane44" AlongDistance 54.9 ExtraOffset 0
sketch "Vertical M5 rail mounting bore (1)" plane through (0, 0, 54.9) normal (0, 0, 1) x axis (1, 0, 0)
  circle C1 centre (30, 85) radius 2.7
extrude "Extrude44" cut sketch "Vertical M5 rail mounting bore (1)" along normal blind 8.2
work_plane "WorkPlane45" AlongDistance 24 ExtraOffset 0
sketch "Close old M5 pivot clearance" plane through (24, 0, 0) normal (1, 0, 0) x axis (0, 0, -1)
  circle C1 centre (-12, -35) radius 2.71
extrude "Extrude45" add sketch "Close old M5 pivot clearance" along normal blind 12
work_plane "WorkPlane46" AlongDistance 23.9 ExtraOffset 0
sketch "M3 follower pivot clearance" plane through (23.9, 0, 0) normal (1, 0, 0) x axis (0, 0, -1)
  circle C1 centre (-12, -35) radius 1.7
extrude "Extrude46" cut sketch "M3 follower pivot clearance" along normal blind 12.2
work_plane "WorkPlane47" AlongDistance 23.9 ExtraOffset 0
